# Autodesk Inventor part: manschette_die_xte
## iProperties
Created: 2004-12
Part Number: manschette_die_xte
Cost Center: 0,005 kg
Document SubType Name: Modeling
Designer: juergen
Authority: 5028 mm^3
Manufacturer: Standard
Standards Organization: Custom
SaveDate: 2004-12-17
SaveTime: 08:45
TotalMass: 0,005 kg
TotalVolume: 5028 mm^3
Author: juergen
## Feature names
1. Extrusion3
2. Extrusion4
3. Runde Anordnung1 [Circular Pattern]
4. Trennen1
5. Trennen2
6. Spiegeln1 [Mirror]
7. Erhebung2
8. Rundung1 [Fillet]
9. Wandstärke1
